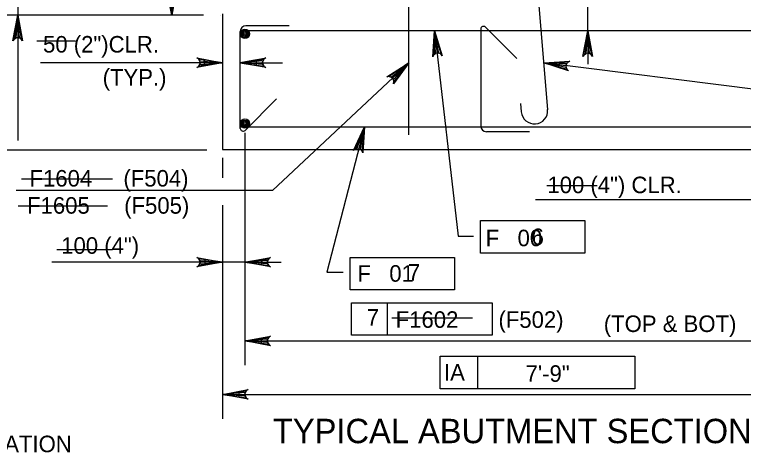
# Model space of a CAD drawing. Extents: x 179 to 454, y -271 to 54.
# Drawn here: x 268.11 to 273.4, y -33.61 to -30.43 of the extents above; entities that cross this region are included whole.
import ezdxf

# ---------------------------------------------------------------- set-up
doc = ezdxf.new("R2010")
doc.units = 0
for name, color, linetype in [('Level 3', 7, 'Continuous'), ('Level 4', 7, 'Continuous'), ('Level 41', 7, 'Continuous'), ('Level 5', 7, 'Continuous'), ('Level 7', 7, 'Continuous'), ('Level 9', 7, 'Continuous')]:
    doc.layers.add(name, color=color, linetype=linetype)

msp = doc.modelspace()

# ---------------------------------------------------------------- linework, layer by layer
at = {"layer": 'Level 3'}
for p, q in [((269.2494, -30.4356), (269.2494, -28.9275)), ((268.1312, -30.3217), (268.1312, -31.3455)), ((269.4797, -30.4356), (267.2547, -30.4356)), ((268.4568, -30.4356), (267.9541, -30.4356)), ((268.1312, -30.5537), (268.1312, -30.6717)), ((271.1569, -30.5477), (271.3282, -32.0403)), ((269.618, -30.7797), (268.2962, -30.7797)), ((269.7466, -30.7797), (270.0525, -30.7797)), ((269.9794, -31.7071), (270.9709, -30.7812)), ((274.4586, -31.0991), (271.9495, -30.7803)), ((270.6487, -31.2449), (270.3748, -32.3015)), ((269.7807, -31.2883), (269.7807, -31.6151)), ((269.7807, -31.2937), (269.7807, -31.8304)), ((269.618, -31.4704), (269.618, -31.6151)), ((269.9794, -31.7071), (268.1209, -31.7071)), ((269.618, -31.8133), (269.618, -33.3651)), ((269.7807, -31.8307), (269.7807, -32.9766)), ((271.4892, -31.9256), (272.2471, -31.9256)), ((271.4892, -32.1618), (271.4892, -31.9256)), ((272.2471, -31.9256), (272.2471, -32.1618)), ((271.3282, -32.0403), (271.4387, -32.0403)), ((272.2471, -32.1618), (271.4892, -32.1618)), ((270.5435, -32.1931), (271.3012, -32.1931)), ((270.5435, -32.4292), (270.5435, -32.1931)), ((271.3012, -32.1931), (271.3012, -32.4292)), ((269.7807, -32.228), (268.3795, -32.228)), ((269.7807, -32.228), (270.0442, -32.228)), ((270.3748, -32.3015), (270.493, -32.3015)), ((271.3012, -32.4292), (270.5435, -32.4292)), ((270.5528, -32.523), (271.5743, -32.523)), ((270.5528, -32.7592), (270.5528, -32.523)), ((270.8164, -32.7592), (270.8164, -32.523)), ((271.5743, -32.523), (271.5743, -32.7592)), ((269.7807, -32.7995), (273.9355, -32.7995)), ((271.5743, -32.7592), (270.5528, -32.7592)), ((271.1975, -32.9114), (271.4712, -32.9114)), ((271.1975, -33.1476), (271.1975, -32.9114)), ((271.4712, -33.1476), (271.4712, -32.9114)), ((271.4712, -32.9114), (272.6095, -32.9114)), ((272.6095, -32.9114), (272.6095, -33.1476)), ((272.6095, -33.1476), (271.1975, -33.1476)), ((269.618, -33.1879), (274.189, -33.1879))]:
    msp.add_line(p, q, dxfattribs=at)
for points in [[(269.2494, -30.4356), (269.2145, -30.2492), (269.2244, -30.2635), (269.2369, -30.2709), (269.2494, -30.2731), (269.2619, -30.2709), (269.2744, -30.2635), (269.2843, -30.2492), (269.2494, -30.4356), (269.2744, -30.2635), (269.2619, -30.2709), (269.2494, -30.4356), (269.2494, -30.2731), (269.2369, -30.2709), (269.2494, -30.4356), (269.2244, -30.2635)], [(268.1312, -30.4356), (268.1662, -30.622), (268.1562, -30.6077), (268.1438, -30.6002), (268.1312, -30.5981), (268.1187, -30.6002), (268.1062, -30.6077), (268.0963, -30.622), (268.1312, -30.4356), (268.1062, -30.6077), (268.1187, -30.6002), (268.1312, -30.4356), (268.1312, -30.5981), (268.1438, -30.6002), (268.1312, -30.4356), (268.1562, -30.6077)], [(271.1569, -30.5477), (271.2129, -30.7289), (271.2013, -30.7157), (271.1881, -30.7098), (271.1754, -30.7091), (271.1633, -30.7127), (271.1517, -30.7214), (271.1434, -30.7368), (271.1569, -30.5477), (271.1517, -30.7214), (271.1633, -30.7127), (271.1569, -30.5477), (271.1754, -30.7091), (271.1881, -30.7098), (271.1569, -30.5477), (271.2013, -30.7157)], [(272.2692, -30.5477), (272.3042, -30.7341), (272.2942, -30.7197), (272.2817, -30.7123), (272.2692, -30.7102), (272.2568, -30.7123), (272.2442, -30.7197), (272.2343, -30.7341), (272.2692, -30.5477), (272.2442, -30.7197), (272.2568, -30.7123), (272.2692, -30.5477), (272.2692, -30.7102), (272.2817, -30.7123), (272.2692, -30.5477), (272.2942, -30.7197)], [(269.618, -30.7797), (269.4316, -30.8146), (269.4459, -30.8047), (269.4533, -30.7922), (269.4555, -30.7797), (269.4533, -30.7672), (269.4459, -30.7547), (269.4316, -30.7447), (269.618, -30.7797), (269.4459, -30.7547), (269.4533, -30.7672), (269.618, -30.7797), (269.4555, -30.7797), (269.4533, -30.7922), (269.618, -30.7797), (269.4459, -30.8047)], [(269.7466, -30.7797), (269.933, -30.7447), (269.9187, -30.7547), (269.9112, -30.7672), (269.9091, -30.7797), (269.9112, -30.7922), (269.9187, -30.8047), (269.933, -30.8146), (269.7466, -30.7797), (269.9187, -30.8047), (269.9112, -30.7922), (269.7466, -30.7797), (269.9091, -30.7797), (269.9112, -30.7672), (269.7466, -30.7797), (269.9187, -30.7547)], [(270.9709, -30.7812), (270.8585, -30.934), (270.8623, -30.9169), (270.8591, -30.9027), (270.8522, -30.8922), (270.8421, -30.8845), (270.8281, -30.8804), (270.8108, -30.8829), (270.9709, -30.7812), (270.8281, -30.8804), (270.8421, -30.8845), (270.9709, -30.7812), (270.8522, -30.8922), (270.8591, -30.9027), (270.9709, -30.7812), (270.8623, -30.9169)], [(271.9494, -30.7802), (272.1388, -30.7691), (272.1232, -30.7772), (272.1143, -30.7887), (272.1107, -30.8008), (272.1112, -30.8134), (272.117, -30.8268), (272.13, -30.8384), (271.9494, -30.7802), (272.117, -30.8268), (272.1112, -30.8134), (271.9494, -30.7802), (272.1107, -30.8008), (272.1143, -30.7887), (271.9494, -30.7802), (272.1232, -30.7772)], [(270.6487, -31.2449), (270.6357, -31.4342), (270.6297, -31.4177), (270.6195, -31.4074), (270.6079, -31.4022), (270.5952, -31.4012), (270.5813, -31.4052), (270.5681, -31.4166), (270.6487, -31.2449), (270.5813, -31.4052), (270.5952, -31.4012), (270.6487, -31.2449), (270.6079, -31.4022), (270.6195, -31.4074), (270.6487, -31.2449), (270.6297, -31.4177)], [(269.618, -32.228), (269.4316, -32.2629), (269.4459, -32.253), (269.4533, -32.2405), (269.4555, -32.228), (269.4533, -32.2155), (269.4459, -32.203), (269.4316, -32.1931), (269.618, -32.228), (269.4459, -32.203), (269.4533, -32.2155), (269.618, -32.228), (269.4555, -32.228), (269.4533, -32.2405), (269.618, -32.228), (269.4459, -32.253)], [(269.7807, -32.228), (269.9671, -32.1931), (269.9527, -32.203), (269.9453, -32.2155), (269.9432, -32.228), (269.9453, -32.2405), (269.9527, -32.253), (269.9671, -32.2629), (269.7807, -32.228), (269.9527, -32.253), (269.9453, -32.2405), (269.7807, -32.228), (269.9432, -32.228), (269.9453, -32.2155), (269.7807, -32.228), (269.9527, -32.203)], [(269.7807, -32.7995), (269.9671, -32.7646), (269.9527, -32.7745), (269.9453, -32.787), (269.9432, -32.7995), (269.9453, -32.812), (269.9527, -32.8245), (269.9671, -32.8344), (269.7807, -32.7995), (269.9527, -32.8245), (269.9453, -32.812), (269.7807, -32.7995), (269.9432, -32.7995), (269.9453, -32.787), (269.7807, -32.7995), (269.9527, -32.7745)], [(269.618, -33.1879), (269.8044, -33.153), (269.7901, -33.1629), (269.7827, -33.1754), (269.7805, -33.1879), (269.7827, -33.2004), (269.7901, -33.2129), (269.8044, -33.2228), (269.618, -33.1879), (269.7901, -33.2129), (269.7827, -33.2004), (269.618, -33.1879), (269.7805, -33.1879), (269.7827, -33.1754), (269.618, -33.1879), (269.7901, -33.1629)]]:
    msp.add_lwpolyline(points, dxfattribs=at)
for points in [[(268.1116, -30.5537), (268.1509, -30.5537), (268.1312, -30.4356)], [(271.1508, -30.6672), (271.19, -30.6628), (271.157, -30.5477)], [(269.4835, -30.7599), (269.4835, -30.7993), (269.6017, -30.7797)], [(269.8647, -30.7993), (269.8647, -30.7599), (269.7466, -30.7797)], [(269.4889, -32.2083), (269.4889, -32.2477), (269.6071, -32.228)], [(269.9042, -32.2477), (269.9042, -32.2083), (269.7861, -32.228)], [(269.8988, -32.7798), (269.8988, -32.8192), (269.7807, -32.7995)], [(269.7362, -33.1683), (269.7362, -33.2076), (269.618, -33.1879)]]:
    msp.add_lwpolyline(points, close=True, dxfattribs=at)
at = {"layer": 'Level 4'}
for p, q in [((272.2697, -30.5477), (272.2697, -30.1887)), ((272.2697, -30.6733), (272.2697, -30.7915)), ((267.146, -31.4129), (269.5045, -31.4129))]:
    msp.add_line(p, q, dxfattribs=at)
msp.add_lwpolyline([(272.2894, -30.6628), (272.2501, -30.6628), (272.2697, -30.5448)], close=True, dxfattribs=at)
at = {"layer": 'Level 41'}
for p, q in [((268.2686, -30.6205), (268.5497, -30.6205)), ((268.1587, -31.6233), (268.8186, -31.6233)), ((271.9715, -31.6722), (272.3382, -31.6722)), ((268.1342, -31.819), (268.7819, -31.819)), ((268.4153, -32.1369), (268.8186, -32.1369)), ((270.8464, -32.6331), (271.433, -32.6331))]:
    msp.add_line(p, q, dxfattribs=at)
at = {"layer": 'Level 5'}
for p, q in [((271.7715, -28.6453), (271.9778, -31.1208)), ((270.9709, -31.3042), (270.9709, -29.6096)), ((270.1017, -30.5118), (269.7876, -30.5118)), ((271.7551, -30.7498), (271.5269, -30.5217)), ((269.7466, -31.2565), (269.7466, -30.5529)), ((274.0601, -30.5477), (269.7469, -30.5477)), ((271.4919, -30.5362), (271.4919, -31.2397)), ((270.0097, -31.0428), (269.7816, -31.271)), ((271.7815, -31.0754), (271.7866, -31.1367)), ((269.7466, -31.2449), (274.0604, -31.2449)), ((271.8471, -31.2807), (271.5329, -31.2807)), ((273.5936, -31.7759), (271.8905, -31.7759))]:
    msp.add_line(p, q, dxfattribs=at)
for centre, radius in [((269.7807, -30.5704), 0.0333), ((269.7807, -30.5704), 0.025), ((269.7807, -30.5704), 0.0167), ((269.7807, -30.5704), 0.00833), ((269.7807, -31.2216), 0.0333), ((269.7807, -31.2216), 0.025), ((269.7807, -31.2216), 0.0167), ((269.7807, -31.2216), 0.00833)]:
    msp.add_circle(centre, radius, dxfattribs=at)
for centre, radius, start, end in [((269.7876, -30.5529), 0.041, 90, 180), ((271.5124, -30.5361), 0.0205, 45, 180), ((271.8822, -31.1287), 0.0959, 184.7636, 4.7636), ((269.7671, -31.2565), 0.0205, 180, 315), ((271.5329, -31.2397), 0.041, 180, 270)]:
    msp.add_arc(centre, radius, start, end, dxfattribs=at)
at = {"layer": 'Level 7'}
msp.add_line((269.6022, -30.4356), (269.6022, -30.4356), dxfattribs=at)
at = {"layer": 'Level 9'}
for p, q in [((269.618, -30.4247), (269.618, -31.4089)), ((269.618, -31.4089), (274.189, -31.4089))]:
    msp.add_line(p, q, dxfattribs=at)

# ---------------------------------------------------------------- texts
at = {"layer": 'Level 3'}
for s, height, p in [('50 (2")CLR.', 0.12, (268.3148, -30.706)), ('(TYP.)', 0.12, (268.7475, -30.9458)), ('F1604', 0.12, (268.2165, -31.679)), ('(F504)', 0.12, (268.8981, -31.679)), ('100 (4") CLR.', 0.12, (271.976, -31.727)), ('F1605', 0.12, (268.199, -31.876)), ('(F505)', 0.12, (268.9039, -31.876)), ('F   00', 0.12, (271.5276, -32.1124)), ('100 (4")', 0.12, (268.4468, -32.1672)), ('F   01', 0.12, (270.5967, -32.3699)), ('F1602', 0.12, (270.8745, -32.7048)), ('(F502)', 0.12, (271.6208, -32.7048)), ('(TOP & BOT)', 0.12, (272.3852, -32.7351)), ('IA', 0.12, (271.2253, -33.0883)), ('TYPICAL ABUTMENT SECTION', 0.177167, (269.9837, -33.5424)), ('DENOTES FINISHED GROUND ELEVATION', 0.12, (265.2511, -33.6077))]:
    msp.add_text(s, height=height, dxfattribs=at).set_placement(p)
at = {"layer": 'Level 41'}
for s, p in [('6', (271.8612, -32.1034)), ('7', (270.9639, -32.362)), ('7', (270.6647, -32.6885)), ('7\'-9"', (271.818, -33.0968))]:
    msp.add_text(s, height=0.12, dxfattribs=at).set_placement(p)

doc.saveas('drawing.dxf')
